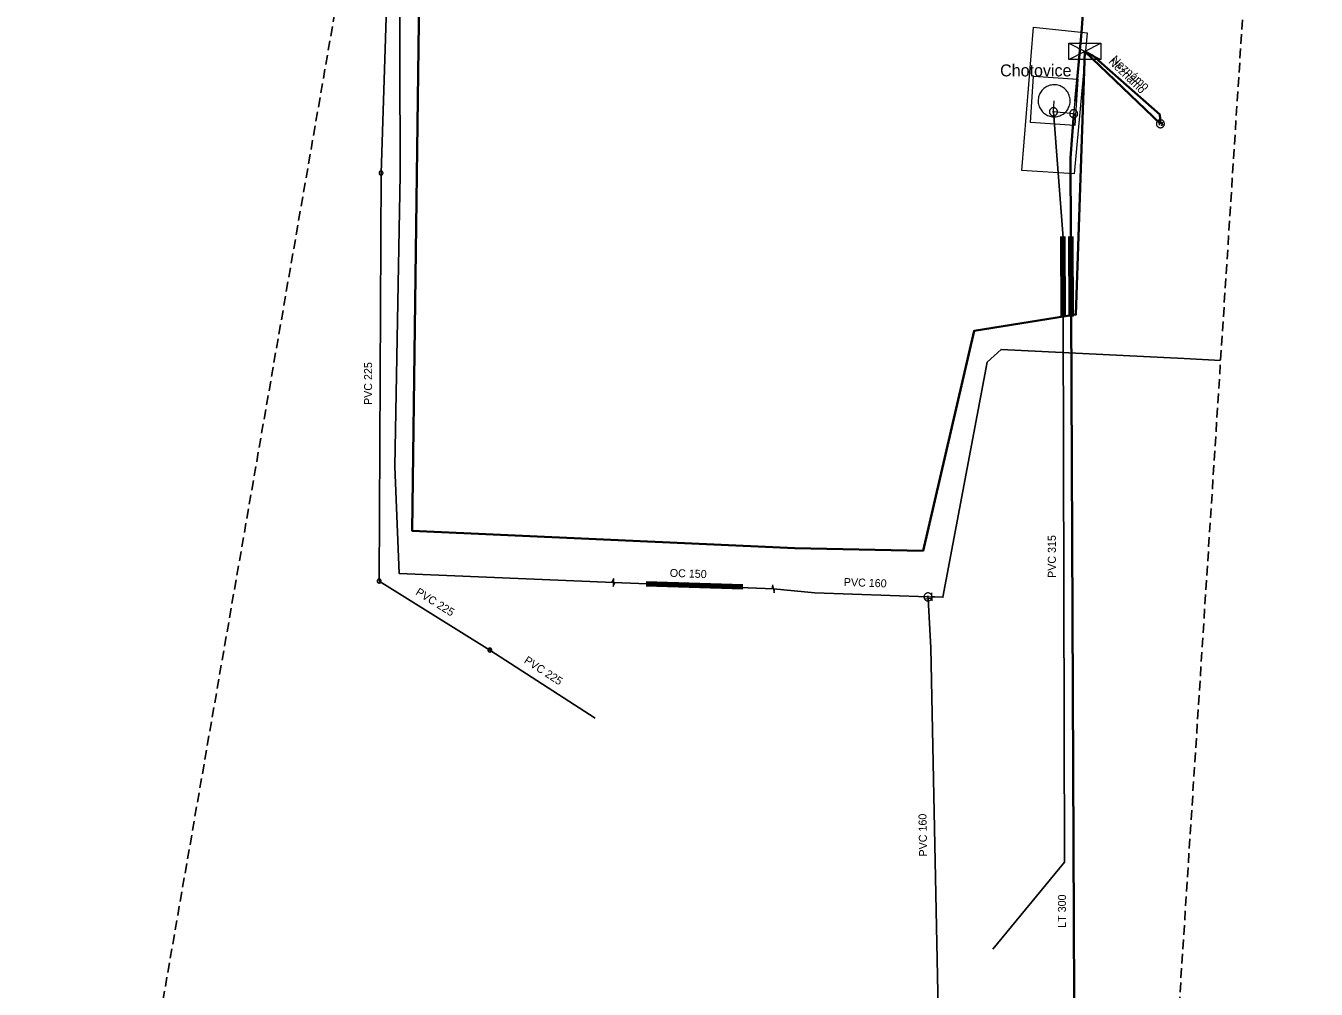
# Model space of a CAD drawing. Extents: x -724358 to -723714, y -973310 to -972026.
# Drawn here: x -723874.8 to -723713.6, y -972299.6 to -972179.2 of the extents above; entities that cross this region are included whole.
import ezdxf

# ---------------------------------------------------------------- set-up
doc = ezdxf.new("R2010")
doc.units = 0
doc.header["$LTSCALE"] = 0.4
doc.linetypes.add('MEDIUM_DASHED', pattern=[4.5, 3, -1.5])
for name, color, linetype, lineweight in [('1', 7, 'Continuous', 13), ('11', 7, 'Continuous', 13), ('14', 7, 'Continuous', 13), ('17', 7, 'Continuous', 25), ('19', 7, 'Continuous', 13), ('2', 7, 'Continuous', 13), ('23', 7, 'Continuous', 13), ('3', 7, 'Continuous', 106), ('34', 7, 'Continuous', 13), ('47', 7, 'Continuous', 13), ('5', 7, 'Continuous', 13)]:
    doc.layers.add(name, color=color, linetype=linetype, lineweight=lineweight)

msp = doc.modelspace()

# ---------------------------------------------------------------- linework, layer by layer
at = {"layer": '1', "linetype": 'MEDIUM_DASHED', "lineweight": 25}
msp.add_lwpolyline([(-723809.944, -972026.35), (-723713.647, -972034.723), (-723734.581, -972361.295), (-724123.956, -973039.561), (-724241.187, -973309.611), (-724358.418, -973148.418), (-723860.186, -972315.24)], close=True, dxfattribs=at)
at = {"layer": '11', "lineweight": 35}
msp.add_line((-723733.109, -972191.412), (-723742.539, -972182.375), dxfattribs=at)
for points in [[(-723742.539, -972182.375), (-723743.653, -972215.278), (-723756.353, -972217.294), (-723762.745, -972244.802), (-723778.784, -972244.465), (-723826.592, -972242.306), (-723825.083, -972127.91), (-723824.595, -972110.591)], [(-723733.109, -972191.412), (-723733.191, -972190.274), (-723741.513, -972182.914), (-723742.539, -972182.375)]]:
    msp.add_lwpolyline(points, dxfattribs=at)
at = {"layer": '14'}
for p, q in [((-723746.467, -972189.923), (-723746.38, -972188.552)), ((-723743.942, -972190.171), (-723743.773, -972188.606)), ((-723743.942, -972190.171), (-723746.467, -972189.923)), ((-723762.141, -972250.574), (-723761.699, -972250.557)), ((-723762.141, -972250.574), (-723762.127, -972250.817))]:
    msp.add_line(p, q, dxfattribs=at)
at = {"layer": '17'}
for p, q in [((-723828.259, -972131.66), (-723830.468, -972197.579)), ((-723830.468, -972197.579), (-723830.698, -972248.589)), ((-723830.698, -972248.589), (-723816.868, -972257.208)), ((-723801.442, -972248.757), (-723781.46, -972249.579)), ((-723816.868, -972257.208), (-723803.709, -972265.739))]:
    msp.add_line(p, q, dxfattribs=at)
at = {"layer": '17', "lineweight": 35}
for points in [[(-723743.773, -972188.606), (-723742.971, -972179.993), (-723740.07, -972139.669), (-723723.419, -972117.993), (-723723.649, -972046.19), (-723722.935, -972033.916)], [(-723743.546, -972376.912), (-723744.353, -972195.662), (-723743.942, -972190.171)]]:
    msp.add_lwpolyline(points, dxfattribs=at)
at = {"layer": '17'}
for points in [[(-723826.673, -972122.54), (-723827.01, -972131.44), (-723828.149, -972167.84), (-723828.07, -972197.809), (-723828.76, -972234.25), (-723828.18, -972247.66), (-723801.442, -972248.757)], [(-723746.467, -972189.923), (-723745.869, -972197.568), (-723745.265, -972205.661), (-723745.265, -972215.649), (-723745.075, -972283.729), (-723754.023, -972294.595)], [(-723761.699, -972250.557), (-723761.269, -972250.544), (-723760.267, -972250.613), (-723754.736, -972221.217), (-723753, -972219.627), (-723730.151, -972220.784), (-723725.589, -972221.021)], [(-723781.46, -972249.579), (-723776.276, -972250.054), (-723762.141, -972250.574)], [(-723762.127, -972250.817), (-723761.789, -972256.934), (-723760.87, -972302.05), (-723760.1, -972327.35), (-723758.879, -972345.77), (-723769.449, -972376.989), (-723783.98, -972421.96), (-723799.539, -972459.809), (-723816.43, -972500.719), (-723818.009, -972505.129)]]:
    msp.add_lwpolyline(points, dxfattribs=at)
at = {"layer": '19'}
for p, q in [((-723744.54, -972183.384), (-723740.538, -972181.366)), ((-723744.54, -972181.366), (-723740.538, -972183.384)), ((-723733.4, -972191.246), (-723733.164, -972191.246)), ((-723733.281, -972191.246), (-723733.281, -972191.601)), ((-723733.109, -972190.927), (-723733.109, -972190.856))]:
    msp.add_line(p, q, dxfattribs=at)
for points in [[(-723744.54, -972181.366), (-723740.538, -972181.366), (-723740.538, -972183.384), (-723744.54, -972183.384)], [(-723732.612, -972191.424), (-723732.616, -972191.371), (-723732.624, -972191.321), (-723732.637, -972191.27), (-723732.656, -972191.221), (-723732.678, -972191.176), (-723732.708, -972191.132), (-723732.74, -972191.091), (-723732.776, -972191.055), (-723732.817, -972191.023), (-723732.861, -972190.993), (-723732.906, -972190.971), (-723732.955, -972190.952), (-723733.006, -972190.939), (-723733.057, -972190.931), (-723733.109, -972190.927), (-723733.161, -972190.931), (-723733.212, -972190.939), (-723733.262, -972190.952), (-723733.311, -972190.971), (-723733.357, -972190.993), (-723733.401, -972191.023), (-723733.441, -972191.055), (-723733.477, -972191.091), (-723733.509, -972191.132), (-723733.539, -972191.176), (-723733.562, -972191.221), (-723733.58, -972191.27), (-723733.594, -972191.321), (-723733.602, -972191.371), (-723733.605, -972191.424), (-723733.602, -972191.476), (-723733.594, -972191.527), (-723733.58, -972191.577), (-723733.562, -972191.626), (-723733.539, -972191.672), (-723733.509, -972191.716), (-723733.477, -972191.756), (-723733.441, -972191.792), (-723733.401, -972191.824), (-723733.357, -972191.853), (-723733.311, -972191.877), (-723733.262, -972191.895), (-723733.212, -972191.909), (-723733.161, -972191.917), (-723733.109, -972191.92), (-723733.057, -972191.917), (-723733.006, -972191.909), (-723732.955, -972191.895), (-723732.906, -972191.877), (-723732.861, -972191.853), (-723732.817, -972191.824), (-723732.776, -972191.792), (-723732.74, -972191.756), (-723732.708, -972191.716), (-723732.678, -972191.672), (-723732.656, -972191.626), (-723732.637, -972191.577), (-723732.624, -972191.527), (-723732.616, -972191.476)]]:
    msp.add_lwpolyline(points, close=True, dxfattribs=at)
msp.add_lwpolyline([(-723733.05, -972191.545), (-723732.995, -972191.601), (-723732.877, -972191.601), (-723732.818, -972191.545), (-723732.818, -972191.486), (-723732.877, -972191.424), (-723732.995, -972191.424), (-723733.05, -972191.361), (-723733.05, -972191.302), (-723732.995, -972191.246), (-723732.877, -972191.246), (-723732.818, -972191.302)], dxfattribs=at)
at = {"layer": '2'}
msp.add_lwpolyline([(-723748.947, -972179.335), (-723742.248, -972180.072), (-723743.883, -972197.697), (-723750.423, -972197.274)], close=True, dxfattribs=at)
at = {"layer": '23'}
for p, q in [((-723830.468, -972197.327), (-723830.468, -972197.841)), ((-723830.698, -972248.337), (-723830.698, -972248.851)), ((-723816.868, -972256.956), (-723816.868, -972257.47))]:
    msp.add_line(p, q, dxfattribs=at)
for points in [[(-723830.216, -972197.581), (-723830.218, -972197.554), (-723830.221, -972197.528), (-723830.227, -972197.503), (-723830.237, -972197.479), (-723830.248, -972197.454), (-723830.263, -972197.432), (-723830.28, -972197.411), (-723830.297, -972197.393), (-723830.318, -972197.376), (-723830.34, -972197.362), (-723830.364, -972197.35), (-723830.388, -972197.34), (-723830.415, -972197.333), (-723830.44, -972197.33), (-723830.466, -972197.328), (-723830.492, -972197.33), (-723830.519, -972197.333), (-723830.544, -972197.339), (-723830.569, -972197.349), (-723830.593, -972197.36), (-723830.614, -972197.375), (-723830.635, -972197.392), (-723830.654, -972197.409), (-723830.67, -972197.43), (-723830.684, -972197.452), (-723830.697, -972197.476), (-723830.707, -972197.5), (-723830.714, -972197.526), (-723830.718, -972197.552), (-723830.719, -972197.578), (-723830.718, -972197.604), (-723830.715, -972197.63), (-723830.708, -972197.656), (-723830.698, -972197.681), (-723830.686, -972197.705), (-723830.672, -972197.726), (-723830.655, -972197.747), (-723830.638, -972197.766), (-723830.617, -972197.782), (-723830.594, -972197.796), (-723830.571, -972197.809), (-723830.546, -972197.819), (-723830.521, -972197.826), (-723830.495, -972197.83), (-723830.469, -972197.831), (-723830.443, -972197.83), (-723830.417, -972197.827), (-723830.391, -972197.82), (-723830.367, -972197.81), (-723830.342, -972197.798), (-723830.32, -972197.784), (-723830.299, -972197.767), (-723830.281, -972197.75), (-723830.264, -972197.729), (-723830.25, -972197.706), (-723830.238, -972197.683), (-723830.228, -972197.658), (-723830.222, -972197.632), (-723830.218, -972197.607)], [(-723830.446, -972248.591), (-723830.448, -972248.564), (-723830.451, -972248.538), (-723830.457, -972248.513), (-723830.467, -972248.489), (-723830.478, -972248.464), (-723830.493, -972248.442), (-723830.51, -972248.421), (-723830.527, -972248.403), (-723830.548, -972248.386), (-723830.57, -972248.372), (-723830.594, -972248.36), (-723830.618, -972248.35), (-723830.645, -972248.343), (-723830.67, -972248.34), (-723830.696, -972248.338), (-723830.722, -972248.34), (-723830.749, -972248.343), (-723830.774, -972248.349), (-723830.799, -972248.359), (-723830.823, -972248.37), (-723830.844, -972248.385), (-723830.865, -972248.402), (-723830.884, -972248.419), (-723830.9, -972248.44), (-723830.914, -972248.462), (-723830.927, -972248.486), (-723830.937, -972248.51), (-723830.944, -972248.536), (-723830.948, -972248.562), (-723830.949, -972248.588), (-723830.948, -972248.614), (-723830.945, -972248.64), (-723830.938, -972248.666), (-723830.928, -972248.691), (-723830.916, -972248.715), (-723830.902, -972248.736), (-723830.885, -972248.757), (-723830.868, -972248.776), (-723830.847, -972248.792), (-723830.824, -972248.806), (-723830.801, -972248.819), (-723830.776, -972248.829), (-723830.751, -972248.836), (-723830.725, -972248.84), (-723830.699, -972248.841), (-723830.673, -972248.84), (-723830.647, -972248.837), (-723830.621, -972248.83), (-723830.597, -972248.82), (-723830.572, -972248.808), (-723830.55, -972248.794), (-723830.529, -972248.777), (-723830.511, -972248.76), (-723830.494, -972248.739), (-723830.48, -972248.716), (-723830.468, -972248.693), (-723830.458, -972248.668), (-723830.452, -972248.642), (-723830.448, -972248.617)], [(-723816.616, -972257.21), (-723816.618, -972257.183), (-723816.621, -972257.157), (-723816.627, -972257.132), (-723816.637, -972257.108), (-723816.648, -972257.083), (-723816.663, -972257.061), (-723816.68, -972257.04), (-723816.697, -972257.022), (-723816.718, -972257.005), (-723816.74, -972256.991), (-723816.764, -972256.978), (-723816.788, -972256.969), (-723816.815, -972256.962), (-723816.84, -972256.959), (-723816.866, -972256.956), (-723816.892, -972256.959), (-723816.919, -972256.962), (-723816.944, -972256.968), (-723816.969, -972256.978), (-723816.993, -972256.989), (-723817.014, -972257.004), (-723817.035, -972257.021), (-723817.054, -972257.038), (-723817.07, -972257.059), (-723817.084, -972257.081), (-723817.097, -972257.105), (-723817.107, -972257.129), (-723817.114, -972257.155), (-723817.118, -972257.181), (-723817.119, -972257.206), (-723817.118, -972257.233), (-723817.115, -972257.259), (-723817.108, -972257.285), (-723817.098, -972257.309), (-723817.086, -972257.334), (-723817.072, -972257.355), (-723817.055, -972257.375), (-723817.038, -972257.395), (-723817.017, -972257.411), (-723816.994, -972257.424), (-723816.971, -972257.438), (-723816.946, -972257.448), (-723816.921, -972257.455), (-723816.895, -972257.459), (-723816.869, -972257.46), (-723816.843, -972257.459), (-723816.817, -972257.456), (-723816.791, -972257.449), (-723816.767, -972257.439), (-723816.742, -972257.427), (-723816.72, -972257.413), (-723816.699, -972257.396), (-723816.681, -972257.379), (-723816.664, -972257.358), (-723816.65, -972257.335), (-723816.638, -972257.312), (-723816.628, -972257.287), (-723816.622, -972257.261), (-723816.618, -972257.236)]]:
    msp.add_lwpolyline(points, close=True, dxfattribs=at)
at = {"layer": '3'}
for p, q in [((-723745.276, -972205.511), (-723745.265, -972215.491)), ((-723744.265, -972215.527), (-723744.31, -972205.527)), ((-723797.342, -972248.927), (-723785.286, -972249.309))]:
    msp.add_line(p, q, dxfattribs=at)
at = {"layer": '3', "lineweight": 100}
for p, q in [((-723745.276, -972205.511), (-723745.265, -972215.491)), ((-723744.265, -972215.527), (-723744.31, -972205.527)), ((-723797.342, -972248.927), (-723785.286, -972249.309))]:
    msp.add_line(p, q, dxfattribs=at)
at = {"layer": '34'}
for p, q in [((-723761.719, -972250.057), (-723761.679, -972251.056)), ((-723761.627, -972250.788), (-723762.626, -972250.844))]:
    msp.add_line(p, q, dxfattribs=at)
at = {"layer": '47'}
for p, q in [((-723801.406, -972248.248), (-723801.636, -972248.704)), ((-723781.558, -972249.08), (-723781.661, -972249.58))]:
    msp.add_line(p, q, dxfattribs=at)
for points in [[(-723746.964, -972189.874), (-723746.966, -972189.926), (-723746.963, -972189.978), (-723746.954, -972190.029), (-723746.941, -972190.08), (-723746.922, -972190.129), (-723746.897, -972190.176), (-723746.868, -972190.219), (-723746.835, -972190.259), (-723746.799, -972190.296), (-723746.758, -972190.329), (-723746.713, -972190.358), (-723746.666, -972190.38), (-723746.618, -972190.399), (-723746.567, -972190.412), (-723746.515, -972190.42), (-723746.463, -972190.422), (-723746.411, -972190.419), (-723746.359, -972190.41), (-723746.309, -972190.397), (-723746.26, -972190.378), (-723746.213, -972190.353), (-723746.169, -972190.324), (-723746.129, -972190.291), (-723746.092, -972190.255), (-723746.06, -972190.214), (-723746.031, -972190.169), (-723746.008, -972190.122), (-723745.99, -972190.074), (-723745.977, -972190.023), (-723745.969, -972189.971), (-723745.967, -972189.919), (-723745.97, -972189.867), (-723745.978, -972189.815), (-723745.992, -972189.765), (-723746.011, -972189.716), (-723746.035, -972189.669), (-723746.064, -972189.625), (-723746.097, -972189.585), (-723746.134, -972189.548), (-723746.175, -972189.516), (-723746.22, -972189.487), (-723746.266, -972189.464), (-723746.315, -972189.446), (-723746.366, -972189.433), (-723746.418, -972189.425), (-723746.47, -972189.423), (-723746.522, -972189.426), (-723746.573, -972189.434), (-723746.624, -972189.448), (-723746.673, -972189.467), (-723746.72, -972189.491), (-723746.763, -972189.52), (-723746.803, -972189.553), (-723746.84, -972189.59), (-723746.873, -972189.631), (-723746.902, -972189.676), (-723746.924, -972189.722), (-723746.943, -972189.771), (-723746.956, -972189.822)], [(-723746.548, -972189.914), (-723746.549, -972189.923), (-723746.548, -972189.932), (-723746.547, -972189.94), (-723746.544, -972189.948), (-723746.541, -972189.956), (-723746.537, -972189.964), (-723746.533, -972189.971), (-723746.527, -972189.978), (-723746.521, -972189.983), (-723746.514, -972189.989), (-723746.507, -972189.994), (-723746.499, -972189.998), (-723746.491, -972190), (-723746.483, -972190.003), (-723746.475, -972190.004), (-723746.466, -972190.005), (-723746.457, -972190.004), (-723746.449, -972190.003), (-723746.441, -972190), (-723746.433, -972189.997), (-723746.425, -972189.993), (-723746.418, -972189.989), (-723746.411, -972189.983), (-723746.405, -972189.977), (-723746.4, -972189.97), (-723746.395, -972189.963), (-723746.391, -972189.955), (-723746.389, -972189.947), (-723746.386, -972189.939), (-723746.385, -972189.931), (-723746.384, -972189.922), (-723746.385, -972189.913), (-723746.386, -972189.905), (-723746.389, -972189.897), (-723746.392, -972189.889), (-723746.395, -972189.881), (-723746.4, -972189.874), (-723746.406, -972189.867), (-723746.412, -972189.861), (-723746.419, -972189.856), (-723746.426, -972189.851), (-723746.434, -972189.847), (-723746.442, -972189.845), (-723746.45, -972189.842), (-723746.458, -972189.841), (-723746.467, -972189.84), (-723746.476, -972189.841), (-723746.484, -972189.842), (-723746.492, -972189.845), (-723746.5, -972189.848), (-723746.508, -972189.851), (-723746.515, -972189.856), (-723746.522, -972189.862), (-723746.527, -972189.868), (-723746.533, -972189.875), (-723746.538, -972189.882), (-723746.542, -972189.89), (-723746.544, -972189.898), (-723746.547, -972189.906)], [(-723743.484, -972190.373), (-723743.466, -972190.324), (-723743.452, -972190.273), (-723743.445, -972190.222), (-723743.441, -972190.17), (-723743.444, -972190.117), (-723743.453, -972190.065), (-723743.467, -972190.015), (-723743.486, -972189.966), (-723743.509, -972189.92), (-723743.538, -972189.876), (-723743.571, -972189.835), (-723743.609, -972189.798), (-723743.649, -972189.765), (-723743.693, -972189.737), (-723743.739, -972189.713), (-723743.788, -972189.695), (-723743.839, -972189.681), (-723743.891, -972189.673), (-723743.942, -972189.67), (-723743.995, -972189.673), (-723744.047, -972189.682), (-723744.098, -972189.696), (-723744.147, -972189.715), (-723744.193, -972189.738), (-723744.236, -972189.767), (-723744.277, -972189.8), (-723744.315, -972189.837), (-723744.347, -972189.878), (-723744.375, -972189.922), (-723744.399, -972189.968), (-723744.417, -972190.017), (-723744.431, -972190.068), (-723744.44, -972190.12), (-723744.442, -972190.171), (-723744.439, -972190.224), (-723744.431, -972190.276), (-723744.417, -972190.327), (-723744.398, -972190.375), (-723744.374, -972190.422), (-723744.345, -972190.465), (-723744.312, -972190.506), (-723744.276, -972190.543), (-723744.234, -972190.576), (-723744.19, -972190.604), (-723744.144, -972190.628), (-723744.095, -972190.646), (-723744.044, -972190.66), (-723743.993, -972190.668), (-723743.941, -972190.671), (-723743.888, -972190.668), (-723743.836, -972190.66), (-723743.786, -972190.646), (-723743.738, -972190.627), (-723743.691, -972190.603), (-723743.647, -972190.574), (-723743.606, -972190.541), (-723743.57, -972190.504), (-723743.536, -972190.463), (-723743.508, -972190.419)], [(-723743.866, -972190.204), (-723743.863, -972190.195), (-723743.861, -972190.187), (-723743.86, -972190.179), (-723743.86, -972190.171), (-723743.86, -972190.162), (-723743.862, -972190.153), (-723743.863, -972190.145), (-723743.867, -972190.137), (-723743.871, -972190.13), (-723743.875, -972190.122), (-723743.881, -972190.115), (-723743.887, -972190.109), (-723743.894, -972190.104), (-723743.9, -972190.099), (-723743.908, -972190.095), (-723743.917, -972190.092), (-723743.925, -972190.09), (-723743.933, -972190.089), (-723743.941, -972190.089), (-723743.95, -972190.089), (-723743.959, -972190.091), (-723743.967, -972190.092), (-723743.975, -972190.096), (-723743.983, -972190.1), (-723743.99, -972190.104), (-723743.997, -972190.11), (-723744.003, -972190.116), (-723744.008, -972190.123), (-723744.013, -972190.129), (-723744.017, -972190.137), (-723744.02, -972190.146), (-723744.022, -972190.154), (-723744.023, -972190.162), (-723744.023, -972190.17), (-723744.023, -972190.179), (-723744.022, -972190.187), (-723744.02, -972190.196), (-723744.016, -972190.204), (-723744.012, -972190.212), (-723744.008, -972190.219), (-723744.002, -972190.226), (-723743.996, -972190.232), (-723743.989, -972190.237), (-723743.983, -972190.242), (-723743.975, -972190.246), (-723743.966, -972190.249), (-723743.958, -972190.251), (-723743.95, -972190.252), (-723743.942, -972190.252), (-723743.933, -972190.252), (-723743.925, -972190.251), (-723743.916, -972190.249), (-723743.908, -972190.245), (-723743.901, -972190.241), (-723743.893, -972190.237), (-723743.886, -972190.231), (-723743.88, -972190.225), (-723743.875, -972190.218), (-723743.87, -972190.212)], [(-723762.117, -972251.073), (-723762.065, -972251.067), (-723762.013, -972251.057), (-723761.964, -972251.041), (-723761.916, -972251.02), (-723761.87, -972250.994), (-723761.827, -972250.963), (-723761.789, -972250.928), (-723761.754, -972250.889), (-723761.723, -972250.848), (-723761.696, -972250.802), (-723761.674, -972250.754), (-723761.659, -972250.705), (-723761.647, -972250.654), (-723761.642, -972250.602), (-723761.641, -972250.55), (-723761.647, -972250.498), (-723761.657, -972250.446), (-723761.673, -972250.396), (-723761.694, -972250.349), (-723761.72, -972250.303), (-723761.751, -972250.26), (-723761.786, -972250.221), (-723761.825, -972250.186), (-723761.866, -972250.155), (-723761.912, -972250.129), (-723761.96, -972250.107), (-723762.01, -972250.091), (-723762.06, -972250.08), (-723762.112, -972250.075), (-723762.164, -972250.074), (-723762.216, -972250.08), (-723762.268, -972250.09), (-723762.318, -972250.105), (-723762.365, -972250.127), (-723762.411, -972250.153), (-723762.454, -972250.183), (-723762.493, -972250.218), (-723762.528, -972250.257), (-723762.559, -972250.299), (-723762.585, -972250.345), (-723762.607, -972250.393), (-723762.623, -972250.442), (-723762.634, -972250.493), (-723762.639, -972250.545), (-723762.64, -972250.597), (-723762.634, -972250.649), (-723762.624, -972250.701), (-723762.609, -972250.75), (-723762.587, -972250.798), (-723762.561, -972250.844), (-723762.531, -972250.887), (-723762.496, -972250.925), (-723762.457, -972250.96), (-723762.415, -972250.991), (-723762.369, -972251.018), (-723762.321, -972251.04), (-723762.273, -972251.055), (-723762.221, -972251.067), (-723762.169, -972251.072)], [(-723762.137, -972250.655), (-723762.128, -972250.655), (-723762.12, -972250.653), (-723762.112, -972250.65), (-723762.104, -972250.647), (-723762.096, -972250.642), (-723762.089, -972250.637), (-723762.083, -972250.632), (-723762.077, -972250.626), (-723762.072, -972250.618), (-723762.068, -972250.611), (-723762.064, -972250.603), (-723762.061, -972250.595), (-723762.06, -972250.587), (-723762.058, -972250.579), (-723762.059, -972250.57), (-723762.059, -972250.561), (-723762.061, -972250.553), (-723762.064, -972250.545), (-723762.067, -972250.537), (-723762.072, -972250.529), (-723762.077, -972250.522), (-723762.082, -972250.516), (-723762.088, -972250.51), (-723762.096, -972250.504), (-723762.103, -972250.501), (-723762.111, -972250.497), (-723762.119, -972250.494), (-723762.127, -972250.493), (-723762.135, -972250.491), (-723762.144, -972250.492), (-723762.153, -972250.492), (-723762.161, -972250.494), (-723762.169, -972250.497), (-723762.177, -972250.5), (-723762.185, -972250.505), (-723762.192, -972250.509), (-723762.198, -972250.515), (-723762.204, -972250.521), (-723762.21, -972250.529), (-723762.213, -972250.536), (-723762.217, -972250.544), (-723762.22, -972250.552), (-723762.221, -972250.56), (-723762.223, -972250.568), (-723762.222, -972250.577), (-723762.222, -972250.586), (-723762.22, -972250.594), (-723762.217, -972250.602), (-723762.214, -972250.61), (-723762.209, -972250.618), (-723762.205, -972250.625), (-723762.199, -972250.631), (-723762.193, -972250.637), (-723762.185, -972250.642), (-723762.178, -972250.646), (-723762.17, -972250.65), (-723762.162, -972250.653), (-723762.154, -972250.654), (-723762.146, -972250.656)]]:
    msp.add_lwpolyline(points, close=True, dxfattribs=at)
for points in [[(-723801.406, -972248.248), (-723801.477, -972249.265), (-723801.247, -972248.809)], [(-723781.558, -972249.08), (-723781.362, -972250.08), (-723781.259, -972249.58)]]:
    msp.add_lwpolyline(points, dxfattribs=at)
at = {"layer": '5'}
for points in [[(-723749.347, -972191.247), (-723748.961, -972185.484), (-723743.411, -972185.856), (-723743.797, -972191.619)], [(-723746.246, -972186.556), (-723746.401, -972186.552), (-723746.555, -972186.559), (-723746.709, -972186.579), (-723746.86, -972186.61), (-723747.009, -972186.653), (-723747.154, -972186.708), (-723747.294, -972186.773), (-723747.43, -972186.85), (-723747.558, -972186.936), (-723747.68, -972187.032), (-723747.793, -972187.137), (-723747.899, -972187.251), (-723747.995, -972187.372), (-723748.081, -972187.501), (-723748.157, -972187.636), (-723748.222, -972187.776), (-723748.277, -972187.921), (-723748.32, -972188.07), (-723748.351, -972188.221), (-723748.372, -972188.375), (-723748.379, -972188.53), (-723748.374, -972188.685), (-723748.359, -972188.839), (-723748.33, -972188.991), (-723748.291, -972189.14), (-723748.239, -972189.287), (-723748.177, -972189.429), (-723748.103, -972189.565), (-723748.02, -972189.696), (-723747.926, -972189.819), (-723747.824, -972189.935), (-723747.713, -972190.043), (-723747.593, -972190.141), (-723747.467, -972190.231), (-723747.332, -972190.31), (-723747.194, -972190.378), (-723747.05, -972190.436), (-723746.902, -972190.482), (-723746.751, -972190.517), (-723746.598, -972190.539), (-723746.444, -972190.551), (-723746.289, -972190.549), (-723746.134, -972190.536), (-723745.982, -972190.511), (-723745.831, -972190.475), (-723745.684, -972190.427), (-723745.54, -972190.368), (-723745.402, -972190.298), (-723745.271, -972190.216), (-723745.145, -972190.125), (-723745.027, -972190.025), (-723744.917, -972189.916), (-723744.816, -972189.799), (-723744.724, -972189.674), (-723744.642, -972189.543), (-723744.571, -972189.405), (-723744.51, -972189.263), (-723744.46, -972189.116), (-723744.422, -972188.966), (-723744.396, -972188.813), (-723744.382, -972188.659), (-723744.379, -972188.504), (-723744.389, -972188.35), (-723744.411, -972188.196), (-723744.444, -972188.046), (-723744.489, -972187.897), (-723744.546, -972187.752), (-723744.612, -972187.613), (-723744.691, -972187.479), (-723744.778, -972187.352), (-723744.877, -972187.232), (-723744.983, -972187.119), (-723745.098, -972187.016), (-723745.221, -972186.921), (-723745.35, -972186.836), (-723745.487, -972186.762), (-723745.628, -972186.699), (-723745.773, -972186.646), (-723745.922, -972186.605), (-723746.074, -972186.574), (-723746.229, -972186.557)]]:
    msp.add_lwpolyline(points, close=True, dxfattribs=at)

# ---------------------------------------------------------------- texts
at = {"layer": '1'}
msp.add_text('Chotovice ', height=1.5, dxfattribs=at).set_placement((-723753.13, -972185.501))
for s, rotation, p in [('Neznámo ', 316, (-723739.669, -972183.76)), ('Neznámo ', 319, (-723739.321, -972183.537)), ('PVC 225 ', 90, (-723831.584, -972226.579)), ('PVC 315 ', 90, (-723746.17, -972248.197)), ('OC 150', 358, (-723794.408, -972248.06)), ('PVC 160 ', 358, (-723772.67, -972249.2)), ('PVC 225 ', 328, (-723826.232, -972250.211)), ('PVC 225 ', 327, (-723812.689, -972258.742)), ('PVC 160 ', 91, (-723762.242, -972283.011)), ('LT 300', 90, (-723744.909, -972291.931))]:
    msp.add_text(s, height=1, rotation=rotation, dxfattribs=at).set_placement(p)

doc.saveas('drawing.dxf')
